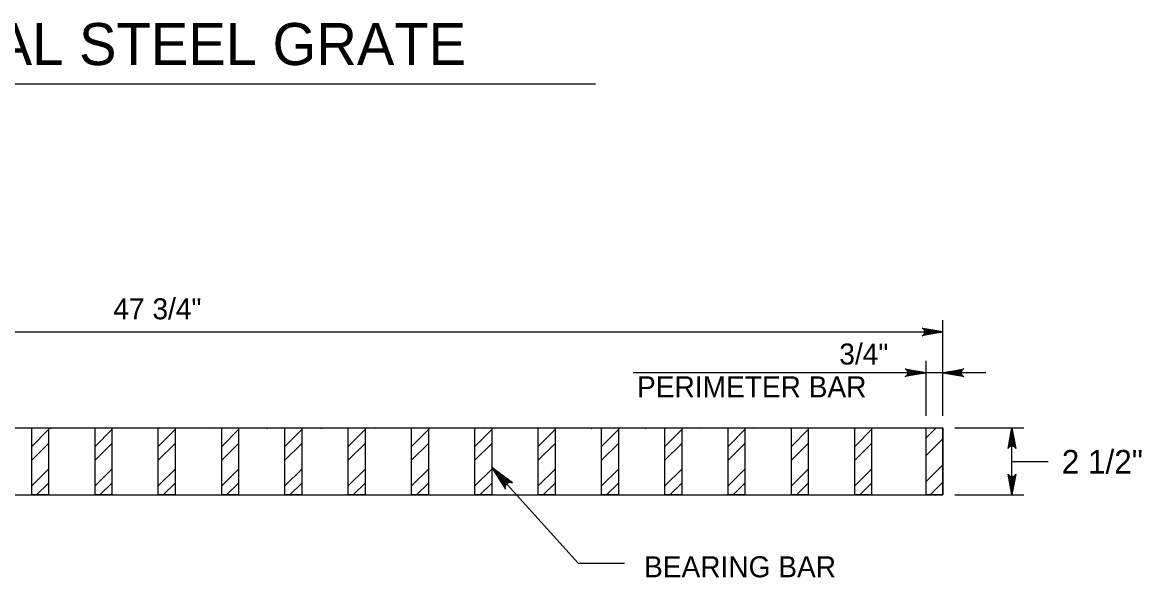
# Model space of a CAD drawing. Extents: x 2087776 to 2104538, y 970919 to 982612.
# Drawn here: x 2096578 to 2097102, y 979641 to 979901 of the extents above; entities that cross this region are included whole.
import ezdxf

# ---------------------------------------------------------------- set-up
doc = ezdxf.new("R2010")
doc.units = 0
doc.layers.add('1', color=7, linetype='Continuous')

msp = doc.modelspace()

# ---------------------------------------------------------------- linework, layer by layer
at = {"layer": '1'}
for p, q in [((2096417.07, 979871.89), (2096846.17, 979871.89)), ((2097009.03, 979716.36), (2097009.03, 979761.18)), ((2096309.27, 979755.67), (2097009.03, 979755.67)), ((2097001.16, 979716.36), (2097001.16, 979742.09)), ((2097009.03, 979716.36), (2097009.03, 979742.09)), ((2097029.12, 979736.58), (2096863.8, 979736.58)), ((2096317.14, 979710.85), (2097009.03, 979710.85)), ((2096582.02, 979679.35), (2096582.02, 979710.85)), ((2096611.69, 979679.35), (2096611.69, 979710.85)), ((2096641.36, 979679.35), (2096641.36, 979710.85)), ((2096671.04, 979679.35), (2096671.04, 979710.85)), ((2096700.71, 979679.35), (2096700.71, 979710.85)), ((2096730.38, 979679.35), (2096730.38, 979710.85)), ((2096760.05, 979679.35), (2096760.05, 979710.85)), ((2096789.72, 979679.35), (2096789.72, 979710.85)), ((2096819.39, 979679.35), (2096819.39, 979710.85)), ((2096849.07, 979679.35), (2096849.07, 979710.85)), ((2096878.74, 979679.35), (2096878.74, 979710.85)), ((2096908.41, 979679.35), (2096908.41, 979710.85)), ((2096938.08, 979679.35), (2096938.08, 979710.85)), ((2096967.75, 979679.35), (2096967.75, 979710.85)), ((2097001.16, 979679.35), (2097001.16, 979710.85)), ((2097009.03, 979679.35), (2097009.03, 979710.85)), ((2097014.55, 979710.85), (2097046.9, 979710.85)), ((2097041.39, 979679.35), (2097041.39, 979710.85)), ((2096797.6, 979692.19), (2096838.09, 979647.4)), ((2096317.14, 979679.35), (2097009.03, 979679.35)), ((2097014.55, 979679.35), (2097046.9, 979679.35))]:
    msp.add_line(p, q, dxfattribs=at)
for points in [[(2097009.03, 979755.67), (2096999.25, 979753.83), (2096999.63, 979754.09), (2097000, 979754.36), (2097000.2, 979754.68), (2097000.39, 979755.01), (2097000.45, 979755.34), (2097000.5, 979755.67), (2097000.45, 979756), (2097000.39, 979756.32), (2097000.2, 979756.65), (2097000, 979756.98), (2096999.63, 979757.24), (2096999.25, 979757.5), (2097009.03, 979755.67), (2096999.63, 979757.24), (2097000, 979756.98), (2097009.03, 979755.67), (2097000.2, 979756.65), (2097000.39, 979756.32), (2097009.03, 979755.67), (2097000.45, 979756), (2097000.5, 979755.67), (2097009.03, 979755.67), (2097000.45, 979755.34), (2097000.39, 979755.01), (2097009.03, 979755.67), (2097000.2, 979754.68), (2097000, 979754.36), (2097009.03, 979755.67), (2096999.63, 979754.09)], [(2097001.16, 979736.58), (2096991.37, 979734.75), (2096991.75, 979735.01), (2096992.13, 979735.27), (2096992.32, 979735.6), (2096992.52, 979735.92), (2096992.57, 979736.25), (2096992.63, 979736.58), (2096992.57, 979736.91), (2096992.52, 979737.24), (2096992.32, 979737.56), (2096992.13, 979737.89), (2096991.75, 979738.15), (2096991.37, 979738.42), (2097001.16, 979736.58), (2096991.75, 979738.15), (2096992.13, 979737.89), (2097001.16, 979736.58), (2096992.32, 979737.56), (2096992.52, 979737.24), (2097001.16, 979736.58), (2096992.57, 979736.91), (2096992.63, 979736.58), (2097001.16, 979736.58), (2096992.57, 979736.25), (2096992.52, 979735.92), (2097001.16, 979736.58), (2096992.32, 979735.6), (2096992.13, 979735.27), (2097001.16, 979736.58), (2096991.75, 979735.01)], [(2097009.03, 979736.58), (2097018.82, 979738.42), (2097018.44, 979738.15), (2097018.07, 979737.89), (2097017.87, 979737.56), (2097017.68, 979737.24), (2097017.62, 979736.91), (2097017.56, 979736.58), (2097017.62, 979736.25), (2097017.68, 979735.92), (2097017.87, 979735.6), (2097018.07, 979735.27), (2097018.44, 979735.01), (2097018.82, 979734.75), (2097009.03, 979736.58), (2097018.44, 979735.01), (2097018.07, 979735.27), (2097009.03, 979736.58), (2097017.87, 979735.6), (2097017.68, 979735.92), (2097009.03, 979736.58), (2097017.62, 979736.25), (2097017.56, 979736.58), (2097009.03, 979736.58), (2097017.62, 979736.91), (2097017.68, 979737.24), (2097009.03, 979736.58), (2097017.87, 979737.56), (2097018.07, 979737.89), (2097009.03, 979736.58), (2097018.44, 979738.15)], [(2096582.02, 979702.1), (2096589.89, 979709.97)], [(2096590.9, 979710.45), (2096591.29, 979710.85)], [(2096611.69, 979702.1), (2096619.57, 979709.97)], [(2096616.23, 979710.45), (2096616.63, 979710.85)], [(2096641.36, 979702.1), (2096649.24, 979709.97)], [(2096641.57, 979710.45), (2096641.96, 979710.85)], [(2096666.9, 979710.45), (2096667.29, 979710.85)], [(2096671.04, 979702.1), (2096678.91, 979709.97)], [(2096692.24, 979710.45), (2096692.63, 979710.85)], [(2096700.71, 979702.1), (2096708.58, 979709.97)], [(2096717.56, 979710.45), (2096717.96, 979710.85)], [(2096730.38, 979702.1), (2096738.25, 979709.97)], [(2096742.9, 979710.45), (2096743.29, 979710.85)], [(2096760.05, 979702.1), (2096767.93, 979709.97)], [(2096768.23, 979710.45), (2096768.63, 979710.85)], [(2096789.72, 979702.1), (2096797.6, 979709.97)], [(2096793.56, 979710.45), (2096793.96, 979710.85)], [(2096818.9, 979710.45), (2096819.29, 979710.85)], [(2096819.39, 979702.1), (2096827.27, 979709.97)], [(2096844.23, 979710.45), (2096844.62, 979710.85)], [(2096849.07, 979702.1), (2096856.94, 979709.97)], [(2096869.57, 979710.45), (2096869.96, 979710.85)], [(2096878.74, 979702.1), (2096886.61, 979709.97)], [(2096894.9, 979710.45), (2096895.29, 979710.85)], [(2096908.41, 979702.1), (2096916.28, 979709.97)], [(2096920.23, 979710.45), (2096920.63, 979710.85)], [(2096938.08, 979702.1), (2096945.96, 979709.97)], [(2096945.57, 979710.45), (2096945.96, 979710.85)], [(2096967.75, 979710.45), (2096968.15, 979710.85)], [(2096967.75, 979702.1), (2096975.63, 979709.97)], [(2097001.16, 979706.11), (2097005.9, 979710.85)], [(2097041.39, 979710.85), (2097043.22, 979701.06), (2097042.96, 979701.44), (2097042.7, 979701.81), (2097042.37, 979702.01), (2097042.05, 979702.2), (2097041.72, 979702.26), (2097041.39, 979702.32), (2097041.06, 979702.26), (2097040.73, 979702.2), (2097040.41, 979702.01), (2097040.08, 979701.81), (2097039.82, 979701.44), (2097039.55, 979701.06), (2097041.39, 979710.85), (2097039.82, 979701.44), (2097040.08, 979701.81), (2097041.39, 979710.85), (2097040.41, 979702.01), (2097040.73, 979702.2), (2097041.39, 979710.85), (2097041.06, 979702.26), (2097041.39, 979702.32), (2097041.39, 979710.85), (2097041.72, 979702.26), (2097042.05, 979702.2), (2097041.39, 979710.85), (2097042.37, 979702.01), (2097042.7, 979701.81), (2097041.39, 979710.85), (2097042.96, 979701.44)], [(2096582.02, 979695.61), (2096589.89, 979703.48)], [(2096611.69, 979695.61), (2096619.57, 979703.48)], [(2096641.36, 979695.61), (2096649.24, 979703.48)], [(2096671.04, 979695.61), (2096678.91, 979703.48)], [(2096700.71, 979695.61), (2096708.58, 979703.48)], [(2096730.38, 979695.61), (2096738.25, 979703.48)], [(2096760.05, 979695.61), (2096767.93, 979703.48)], [(2096789.72, 979695.61), (2096797.6, 979703.48)], [(2096819.39, 979695.61), (2096827.27, 979703.48)], [(2096849.07, 979695.61), (2096856.94, 979703.48)], [(2096878.74, 979695.61), (2096886.61, 979703.48)], [(2096908.41, 979695.61), (2096916.28, 979703.48)], [(2096938.08, 979695.61), (2096945.96, 979703.48)], [(2096967.75, 979695.61), (2096975.63, 979703.48)], [(2097001.16, 979697.76), (2097009.03, 979705.64)], [(2096797.6, 979692.19), (2096804.01, 979682.04), (2096803.93, 979682.58), (2096803.86, 979683.13), (2096803.99, 979683.57), (2096804.12, 979684.01), (2096804.36, 979684.33), (2096804.6, 979684.65), (2096804.94, 979684.87), (2096805.28, 979685.09), (2096805.73, 979685.19), (2096806.18, 979685.29), (2096806.72, 979685.17), (2096807.26, 979685.05), (2096797.6, 979692.19), (2096806.72, 979685.17), (2096806.18, 979685.29), (2096797.6, 979692.19), (2096805.73, 979685.19), (2096805.28, 979685.09), (2096797.6, 979692.19), (2096804.94, 979684.87), (2096804.6, 979684.65), (2096797.6, 979692.19), (2096804.36, 979684.33), (2096804.12, 979684.01), (2096797.6, 979692.19), (2096803.99, 979683.57), (2096803.86, 979683.13), (2096797.6, 979692.19), (2096803.93, 979682.58)], [(2097001.16, 979685.66), (2097009.03, 979693.53)], [(2097058.42, 979694.87), (2097041.39, 979694.87)], [(2096582.02, 979683.62), (2096589.89, 979691.5)], [(2096611.69, 979683.62), (2096619.57, 979691.5)], [(2096641.36, 979683.62), (2096649.24, 979691.5)], [(2096671.04, 979683.62), (2096678.91, 979691.5)], [(2096700.71, 979683.62), (2096708.58, 979691.5)], [(2096730.38, 979683.62), (2096738.25, 979691.5)], [(2096760.05, 979683.62), (2096767.93, 979691.5)], [(2096789.72, 979683.62), (2096797.6, 979691.5)], [(2096819.39, 979683.62), (2096827.27, 979691.5)], [(2096849.07, 979683.62), (2096856.94, 979691.5)], [(2096878.74, 979683.62), (2096886.61, 979691.5)], [(2096908.41, 979683.62), (2096916.28, 979691.5)], [(2096938.08, 979683.62), (2096945.96, 979691.5)], [(2096967.75, 979683.62), (2096975.63, 979691.5)], [(2097041.39, 979679.35), (2097039.55, 979689.13), (2097039.82, 979688.76), (2097040.08, 979688.38), (2097040.41, 979688.19), (2097040.73, 979687.99), (2097041.06, 979687.94), (2097041.39, 979687.88), (2097041.72, 979687.94), (2097042.05, 979687.99), (2097042.37, 979688.19), (2097042.7, 979688.38), (2097042.96, 979688.76), (2097043.22, 979689.13), (2097041.39, 979679.35), (2097042.96, 979688.76), (2097042.7, 979688.38), (2097041.39, 979679.35), (2097042.37, 979688.19), (2097042.05, 979687.99), (2097041.39, 979679.35), (2097041.72, 979687.94), (2097041.39, 979687.88), (2097041.39, 979679.35), (2097041.06, 979687.94), (2097040.73, 979687.99), (2097041.39, 979679.35), (2097040.41, 979688.19), (2097040.08, 979688.38), (2097041.39, 979679.35), (2097039.82, 979688.76)], [(2096584.32, 979679.35), (2096589.89, 979684.92)], [(2096613.99, 979679.35), (2096619.57, 979684.92)], [(2096643.67, 979679.35), (2096649.24, 979684.92)], [(2096673.34, 979679.35), (2096678.91, 979684.92)], [(2096703.01, 979679.35), (2096708.58, 979684.92)], [(2096732.68, 979679.35), (2096738.25, 979684.92)], [(2096762.35, 979679.35), (2096767.93, 979684.92)], [(2096792.03, 979679.35), (2096797.6, 979684.92)], [(2096821.7, 979679.35), (2096827.27, 979684.92)], [(2096851.37, 979679.35), (2096856.94, 979684.92)], [(2096881.04, 979679.35), (2096886.61, 979684.92)], [(2096910.71, 979679.35), (2096916.28, 979684.92)], [(2096940.39, 979679.35), (2096945.96, 979684.92)], [(2096970.06, 979679.35), (2096975.63, 979684.92)], [(2097003.09, 979679.35), (2097009.03, 979685.29)], [(2096838.09, 979647.4), (2096859.86, 979647.4)]]:
    msp.add_lwpolyline(points, dxfattribs=at)
for points in [[(2096582.02, 979679.35), (2096582.02, 979710.85), (2096589.89, 979710.85), (2096589.89, 979679.35)], [(2096611.69, 979679.35), (2096611.69, 979710.85), (2096619.57, 979710.85), (2096619.57, 979679.35)], [(2096641.36, 979679.35), (2096641.36, 979710.85), (2096649.24, 979710.85), (2096649.24, 979679.35)], [(2096671.04, 979679.35), (2096671.04, 979710.85), (2096678.91, 979710.85), (2096678.91, 979679.35)], [(2096700.71, 979679.35), (2096700.71, 979710.85), (2096708.58, 979710.85), (2096708.58, 979679.35)], [(2096730.38, 979679.35), (2096730.38, 979710.85), (2096738.25, 979710.85), (2096738.25, 979679.35)], [(2096760.05, 979679.35), (2096760.05, 979710.85), (2096767.93, 979710.85), (2096767.93, 979679.35)], [(2096789.72, 979679.35), (2096789.72, 979710.85), (2096797.6, 979710.85), (2096797.6, 979679.35)], [(2096819.39, 979679.35), (2096819.39, 979710.85), (2096827.27, 979710.85), (2096827.27, 979679.35)], [(2096849.07, 979679.35), (2096849.07, 979710.85), (2096856.94, 979710.85), (2096856.94, 979679.35)], [(2096878.74, 979679.35), (2096878.74, 979710.85), (2096886.61, 979710.85), (2096886.61, 979679.35)], [(2096908.41, 979679.35), (2096908.41, 979710.85), (2096916.28, 979710.85), (2096916.28, 979679.35)], [(2096938.08, 979679.35), (2096938.08, 979710.85), (2096945.96, 979710.85), (2096945.96, 979679.35)], [(2096967.75, 979679.35), (2096967.75, 979710.85), (2096975.63, 979710.85), (2096975.63, 979679.35)], [(2097001.16, 979679.35), (2097001.16, 979710.85), (2097009.03, 979710.85), (2097009.03, 979679.35)]]:
    msp.add_lwpolyline(points, close=True, dxfattribs=at)

# ---------------------------------------------------------------- texts
for s, height, p in [('STRUCTURAL STEEL GRATE', 19.685, (2096419.92, 979880.64)), ('47 3/4"', 9.843, (2096620.29, 979761.61)), ('3/4"', 9.843, (2096960.48, 979740.43)), ('PERIMETER BAR', 9.8425, (2096865.69, 979725.07)), ('2 1/2"', 11.024, (2097064.75, 979689.4)), ('BEARING BAR', 9.8425, (2096868.98, 979640.81))]:
    msp.add_text(s, height=height, dxfattribs=at).set_placement(p)

doc.saveas('drawing.dxf')
